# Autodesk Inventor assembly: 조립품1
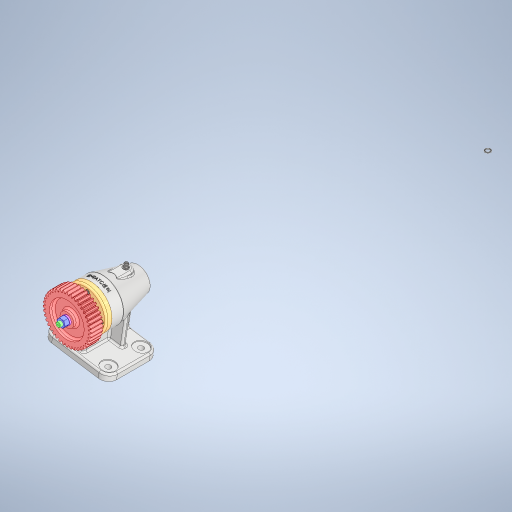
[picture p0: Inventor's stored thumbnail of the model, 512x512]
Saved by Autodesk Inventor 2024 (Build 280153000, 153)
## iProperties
Created: 2024-12
Part Number: 조립품1
Document SubType Name: Assembly
Designer: user
Author: user
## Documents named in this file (15)
- C:\Users\user\Desktop\741204V1017\조립품1.iam
- C:\Users\user\Desktop\741204V1017\본체.ipt
- C:\Users\user\Desktop\741204V1017\그리스 니플 M6x0.75\그리스 니플 M6x0.75.ipt
- C:\Users\user\Desktop\741204V1017\스퍼기어\스퍼기어.ipt
- C:\Users\user\Desktop\741204V1017\스프링 와셔 M8\스프링 와셔 M8.ipt
- C:\Users\user\Desktop\741204V1017\실링\실링.ipt
- C:\Users\user\Desktop\741204V1017\앵귤러 볼 베어링 7003A\앵귤러 볼 베어링 7003A.ipt
- C:\Users\user\Desktop\741204V1017\앵귤러 볼 제어링 7204A\앵귤러 볼 제어링 7204A.ipt
- C:\Users\user\Desktop\741204V1017\오일 실 20 32 8\오일 실 20 32 8.ipt
- C:\Users\user\Desktop\741204V1017\육각 너트 M8\육각 너트 M8.ipt
- C:\Users\user\Desktop\741204V1017\육각 소켓 머리 볼트 M4x10\육각 소켓 머리 볼트 M4x10.ipt
- C:\Users\user\Desktop\741204V1017\축\축.ipt
- C:\Users\user\Desktop\741204V1017\커버\커버.ipt
- C:\Users\user\Desktop\741204V1017\평와셔 M8\평와셔 M8.ipt
- C:\Users\user\Desktop\741204V1017\평행 키 4x4x14\평행 키 4x4x14.ipt
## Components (1 placed, 1 different names)
1. 그리스 니플 M6x0.75:2
